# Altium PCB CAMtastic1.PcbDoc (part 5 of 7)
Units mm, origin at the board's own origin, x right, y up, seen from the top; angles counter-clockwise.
Board outline 150.22 x 135.24 mm, 5 copper layers (Top Layer, Layer 1, Mid-Layer 1, Layer 2, Bottom Layer), stack 0.461 mm thick; 0 components, 362 nets, 2885 pads, 0 vias.
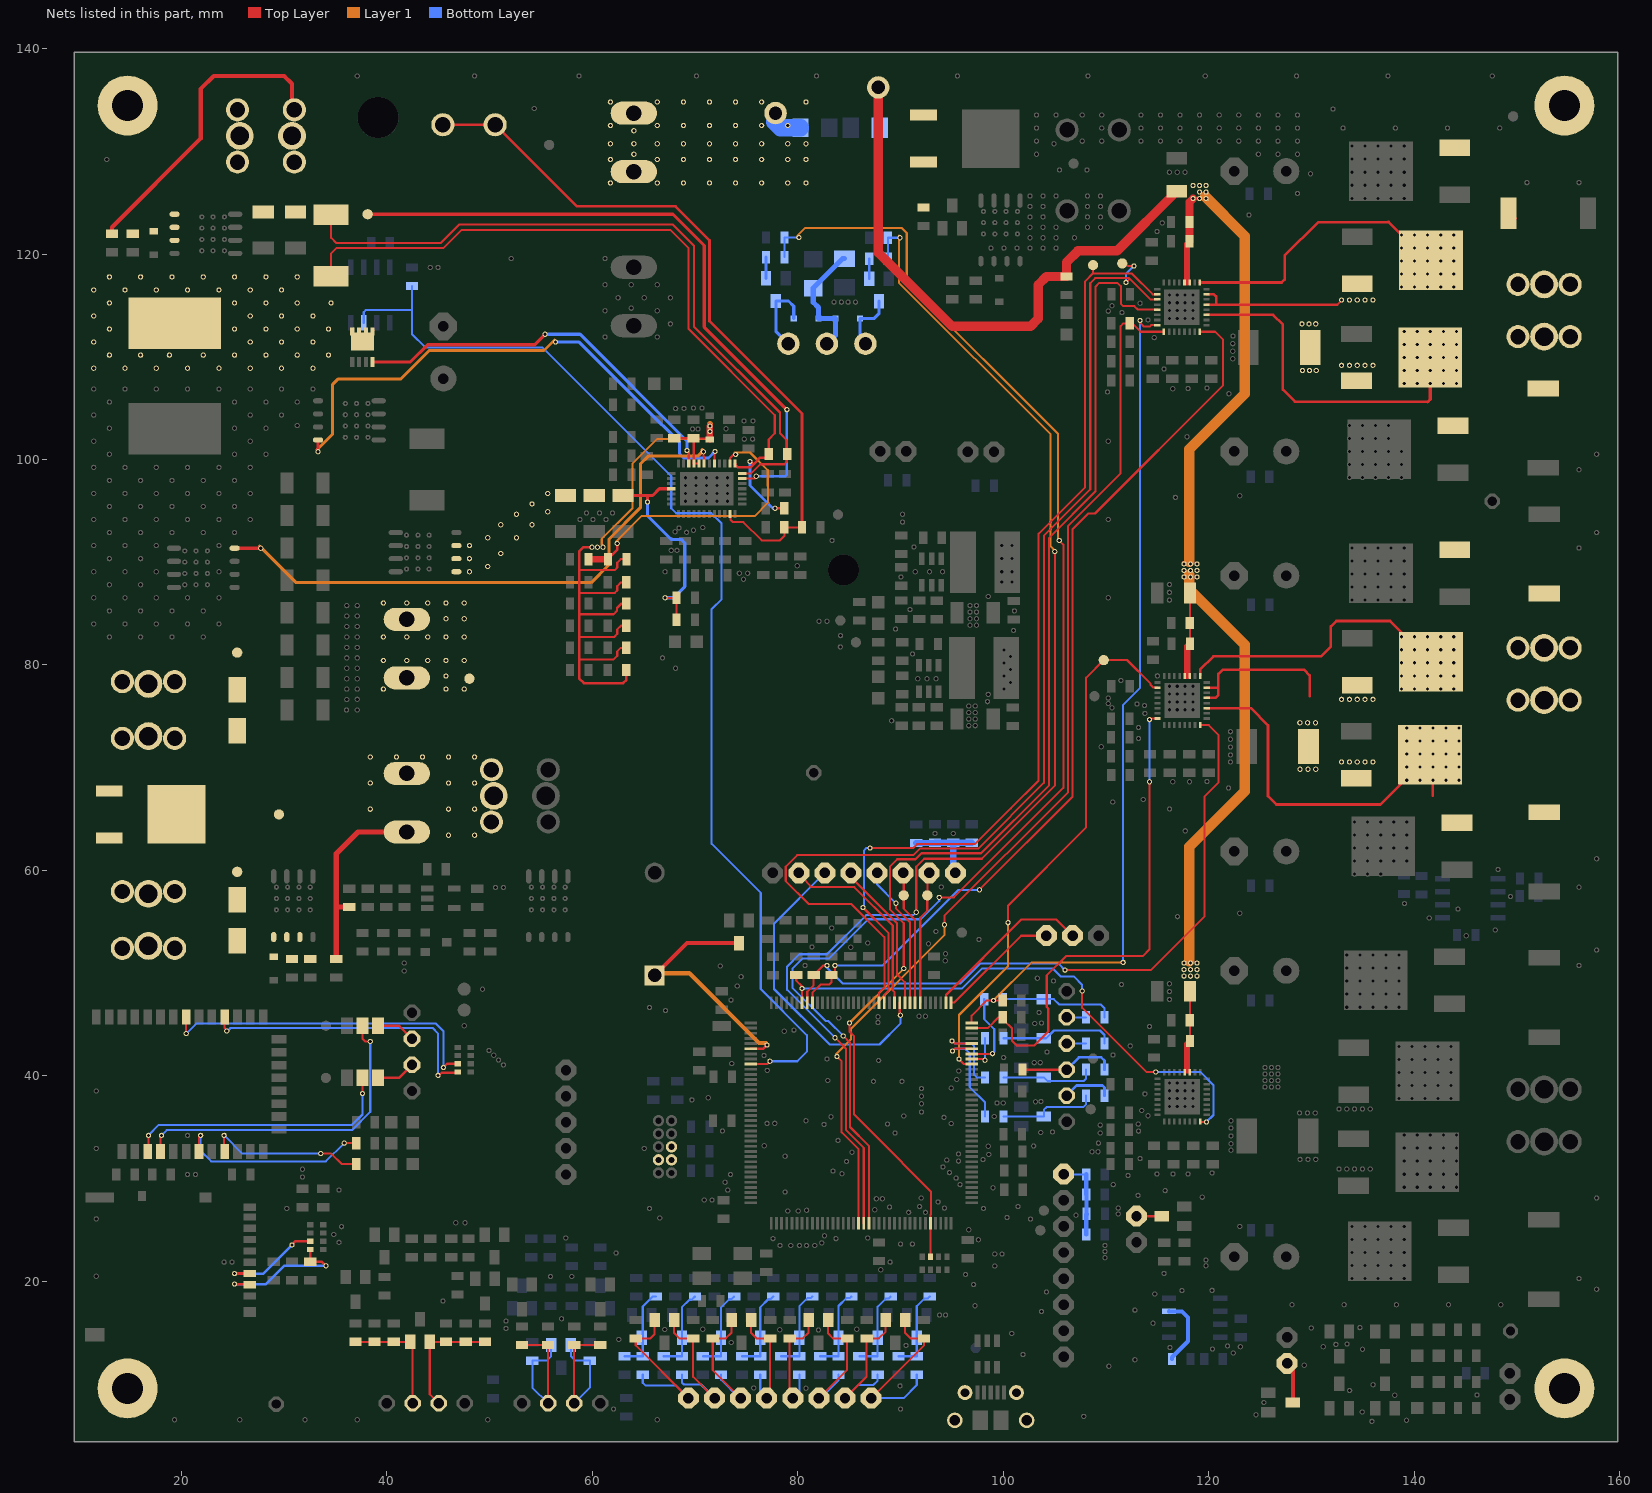
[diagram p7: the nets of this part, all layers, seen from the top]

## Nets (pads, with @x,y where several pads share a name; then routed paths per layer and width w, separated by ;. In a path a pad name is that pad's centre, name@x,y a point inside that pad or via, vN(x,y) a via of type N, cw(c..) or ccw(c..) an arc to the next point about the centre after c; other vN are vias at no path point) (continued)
$Net72: pad.1@25.167,19.736 pad.1@26.642,19.668 pad.1@32.533,21.906 pad.1@32.533,23.108 pad.1@34.057,21.514 | length 14
  Top Layer w0.254: pad.1@25.167,19.736 25.201,19.702 26.608,19.702 pad.1@26.642,19.668 ; pad.1@32.533,23.108 pad.1@32.533,21.906 33.665,21.906 pad.1@34.057,21.514
  Bottom Layer w0.254: pad.1@25.167,19.736 28.215,19.736 29.993,21.514 pad.1@34.057,21.514
$Net73: pad.1@24.151,34.214 pad.1@24.204,32.631 pad.1@33.549,32.436 pad.1@37.001,31.42 | length 15.6
  Top Layer w0.203: pad.1@24.151,34.214 24.151,32.685 pad.1@24.204,32.631 ; pad.1@33.549,32.436 34.565,32.436 35.581,31.42 pad.1@37.001,31.42
  Bottom Layer w0.203: pad.1@24.151,34.214 25.929,32.436 pad.1@33.549,32.436
$Net74: pad.1@21.705,32.631 pad.1@21.865,34.214 pad.1@35.835,33.452 pad.1@37.001,33.452 | length 19.5
  Top Layer w0.203: pad.1@21.705,32.631 21.705,34.054 pad.1@21.865,34.214 ; pad.1@35.835,33.452 pad.1@37.001,33.452
  Bottom Layer w0.203: pad.1@21.865,34.214 21.865,32.69 22.881,31.674 34.057,31.674 pad.1@35.835,33.452
$Net75: pad.1@16.706,32.631 pad.1@16.785,34.214 pad.1@37.613,38.278 pad.1@37.613,39.802 | length 26.8
  Top Layer w0.203: pad.1@16.706,32.631 16.785,32.71 pad.1@16.785,34.214 ; pad.1@37.613,38.278 pad.1@37.613,39.802
  Bottom Layer w0.203: pad.1@16.785,34.214 17.801,35.23 36.597,35.23 37.613,36.246 pad.1@37.613,38.278
$Net76: pad.1@24.204,45.738 pad.1@24.405,44.374 pad.1@44.979,40.056 pad.1@46.893,40.38 | length 28.5
  Top Layer w0.203: pad.1@24.204,45.738 24.204,44.657 24.405,44.456 pad.1@24.405,44.374 ; pad.1@44.979,40.056 45.061,40.056 45.315,40.31 46.823,40.31 pad.1@46.893,40.38
  Bottom Layer w0.203: pad.1@24.405,44.374 24.487,44.374 24.773,44.66 44.438,44.66 44.979,44.12 pad.1@44.979,40.056
$Net77: pad.1@25.167,20.752 pad.1@26.642,20.768 pad.1@30.755,23.546 pad.1@32.533,23.908 | length 10.2
  Top Layer w0.254: pad.1@25.167,20.752 25.174,20.76 26.634,20.76 pad.1@26.642,20.768 ; pad.1@30.755,23.546 31.117,23.908 pad.1@32.533,23.908
  Bottom Layer w0.254: pad.1@25.167,20.752 27.961,20.752 pad.1@30.755,23.546
$Net78: pad.1@17.956,32.631 pad.1@18.055,34.214 pad.1@37.613,44.882 pad.1@38.375,43.358 | length 31.9
  Top Layer w0.203: pad.1@17.956,32.631 17.956,34.115 pad.1@18.055,34.214 ; pad.1@37.613,44.882 37.613,43.612 37.867,43.358 pad.1@38.375,43.358
  Bottom Layer w0.203: pad.1@18.055,34.214 18.563,34.722 36.597,34.722 38.375,36.5 pad.1@38.375,43.358
$Net79: pad.1@20.455,44.12 pad.1@20.455,45.738 pad.1@45.487,40.818 pad.1@46.893,41.18 | length 32.5
  Top Layer w0.203: pad.1@20.455,44.12 pad.1@20.455,45.738 ; pad.1@45.487,40.818 45.849,41.18 pad.1@46.893,41.18
  Bottom Layer w0.203: pad.1@20.455,44.12 21.425,45.09 44.77,45.09 45.487,44.374 pad.1@45.487,40.818
$Net80: pad.1@19.524,65.456 pad.1@29.485,65.456 pad.1@35.073,51.37 pad.1@36.343,56.428 pad.1@38.375,65.964 pad.1@38.375,68.504 pad.1@38.375,71.044 pad.1@40.915,71.044 pad.1@41.931,63.742 pad.1@41.931,69.442 pad.1@43.455,71.044 pad.1@45.995,63.424 pad.1@45.995,65.964 pad.1@45.995,68.504 pad.1@45.995,71.044 pad.1@48.535,63.424 pad.1@48.535,65.964 pad.1@48.535,68.504 pad.1@48.535,71.044 pad.1@50.17,64.718 pad.1@50.17,69.798 pad.1@50.395,67.258 | length 19.3
  Top Layer w0.508: pad.1@35.073,51.37 35.073,56.508 ; pad.1@36.343,56.428 35.153,56.428 35.073,56.508 ; pad.1@41.931,63.742 37.169,63.742 35.073,61.646 35.073,56.508
$Net82: pad.1@86.339,56.388 pad.1@87.024,62.179 pad.1@88.411,47.142 pad.1@108.729,118.923 pad.1@114.98,116.083 | length 95.3
  Top Layer w0.203: pad.1@86.339,56.388 88.828,53.899 88.828,48.311 88.411,47.894 pad.1@88.411,47.142 ; pad.1@87.024,62.179 91.241,62.179 91.622,62.56 97.21,62.56 100.715,66.04 103.433,68.758 103.433,92.786 107.954,97.307 107.954,117.348 108.716,118.11 ; pad.1@108.729,118.923 108.729,118.123 108.716,118.11 ; pad.1@114.98,116.083 114.888,116.078 114.533,116.078 112.501,118.11 108.716,118.11
  Bottom Layer w0.203: pad.1@86.339,56.388 86.44,56.49 86.44,61.951 86.669,62.179 pad.1@87.024,62.179
$Net83: pad.1@87.705,59.758 pad.1@89.539,56.807 pad.1@90.911,47.142 | length 13.9
  Top Layer w0.203: pad.1@89.539,56.807 89.539,56.337 90.911,54.966 90.911,47.244 pad.1@90.911,47.142
  Bottom Layer w0.203: pad.1@87.705,59.758 87.705,58.641 pad.1@89.539,56.807
$Net84: pad.1@83.621,43.713 pad.1@86.411,25.654 pad.1@88.754,119.558 pad.1@88.754,121.59 pad.1@89.937,121.59 pad.1@91.52,55.931 pad.1@105.008,91.034 | length 126.8
  Top Layer w0.203: pad.1@83.621,43.713 84.662,42.672 84.662,34.747 86.411,32.999 pad.1@86.411,25.654 ; pad.1@91.52,55.931 91.52,60.376 92.282,61.138 97.896,61.138 105.008,68.25 pad.1@105.008,91.034
  Layer 1 w0.203: pad.1@89.83,121.793 89.83,117.221 104.596,102.455 104.596,91.542 pad.1@104.901,91.237
  Bottom Layer w0.203: pad.1@83.621,43.713 78.947,48.387 78.947,50.648 80.141,51.841 82.833,51.841 86.643,55.651 91.241,55.651 pad.1@91.52,55.931 ; pad.1@88.754,119.558 pad.1@88.754,121.59 pad.1@89.937,121.59
$Net85: pad.1@78.705,119.705 pad.1@78.705,121.61 pad.1@80.09,121.615 pad.1@84.408,43.891 pad.1@86.911,25.654 pad.1@93.755,57.379 pad.1@105.439,92.126 | length 136.4
  Top Layer w0.203: pad.1@84.408,43.891 85.069,43.231 85.069,35.027 86.911,33.184 pad.1@86.911,25.654 ; pad.1@93.755,57.379 95.178,57.379 105.846,68.047 105.846,91.719 pad.1@105.439,92.126
  Layer 1 w0.203: pad.1@79.984,121.818 80.72,122.555 90.084,122.555 90.592,122.047 90.592,117.221 105.333,102.48 pad.1@105.333,92.329
  Bottom Layer w0.203: pad.1@78.705,119.705 78.705,121.56 pad.1@78.755,121.61 ; pad.1@78.705,121.61 pad.1@78.755,121.61 ; pad.1@80.09,121.615 80.085,121.61 pad.1@78.755,121.61 ; pad.1@84.408,43.891 82.96,45.339 82.706,45.339 79.455,48.59 79.455,50.419 80.471,51.435 83.037,51.435 86.847,55.245 91.952,55.245 93.755,57.048 pad.1@93.755,57.379
$Net86: pad.1@83.799,41.885 pad.1@85.911,25.654 pad.1@94.263,54.712 pad.1@112.311,113.259 pad.1@115.63,112.433 | length 104.2
  Top Layer w0.203: pad.1@83.799,41.885 84.256,41.427 84.256,34.497 85.911,32.842 pad.1@85.911,25.654 ; pad.1@94.263,54.712 94.263,55.575 106.303,67.615 106.303,93.548 111.408,98.654 111.408,112.979 111.688,113.259 pad.1@112.311,113.259 112.551,113.259 113.377,112.433 pad.1@115.63,112.433
  Layer 1 w0.203: pad.1@83.692,42.088 85.165,43.561 85.165,44.602 94.263,53.7 pad.1@94.263,54.712 ; pad.1@94.347,54.712 94.347,54.725 94.36,54.712 pad.1@94.347,54.712
$Net87: pad.1@85.018,45.161 pad.1@90.301,50.444 pad.1@92.898,22.393 pad.1@92.911,25.654 pad.1@114.98,114.583 | length 121.4
  Top Layer w0.203: pad.1@85.018,45.161 85.018,44.323 85.475,43.866 85.475,36.246 87.405,34.315 92.943,28.753 92.943,26.518 92.911,26.486 pad.1@92.911,25.654 92.911,22.405 pad.1@92.898,22.393 ; pad.1@90.301,50.444 90.301,54.864 88.98,56.185 88.98,60.401 89.666,61.087 91.444,61.087 92.028,61.671 97.819,61.671 104.449,68.301 104.449,92.38 108.97,96.901 108.97,116.815 109.351,117.196 111.104,117.196 111.434,116.865 111.434,115.164 111.662,114.935 112.755,114.935 113.106,114.583 pad.1@114.98,114.583
  Layer 1 w0.203: pad.1@85.027,45.152 pad.1@90.311,50.435
$Net88: pad.1@82.625,59.758 pad.1@89.911,47.142 pad.1@89.971,45.898 | length 30.8
  Top Layer w0.203: pad.1@89.911,47.142 89.911,45.958 pad.1@89.971,45.898
  Bottom Layer w0.203: pad.1@82.625,59.758 77.677,54.81 77.677,54.712 77.677,54.635 77.677,48.463 83.087,43.053 87.939,43.053 89.971,45.085 pad.1@89.971,45.898
$Net89: pad.1@95.686,41.631 pad.1@96.905,41.148 pad.1@100.461,54.915 pad.1@109.77,80.48 pad.1@115.005,77.792 | length 52.5
  Top Layer w0.203: pad.1@95.686,41.631 96.168,41.148 pad.1@96.905,41.148 ; pad.1@100.461,54.915 100.461,56.591 108.056,64.186 108.056,78.765 pad.1@109.77,80.48 112.031,80.48 114.304,78.207 114.304,78.105 114.617,77.792 pad.1@115.005,77.792
  Layer 1 w0.203: pad.1@95.686,41.727 95.686,45.924 100.461,50.699 pad.1@100.461,54.915
  Layer 1 w0.254: pad.1@95.686,41.631 pad.1@95.686,41.727
$Net90: pad.1@95.051,42.418 pad.1@96.905,42.648 pad.1@98.215,36.043 | length 10.7
  Top Layer w0.203: pad.1@95.051,42.418 95.281,42.648 pad.1@96.905,42.648
  Bottom Layer w0.203: pad.1@95.051,42.418 95.279,42.647 96.27,42.647 96.727,42.189 96.727,38.913 98.215,37.425 pad.1@98.215,36.043
$Net91: pad.1@95,43.409 pad.1@96.905,43.148 pad.1@98.215,39.853 | length 8.3
  Top Layer w0.203: pad.1@95,43.409 95.26,43.148 pad.1@96.905,43.148
  Bottom Layer w0.203: pad.1@95,43.409 95.26,43.148 96.905,43.148 97.159,42.894 97.159,40.107 97.413,39.853 pad.1@98.215,39.853
$Net92: pad.1@96.905,41.648 pad.1@98.2,41.529 pad.1@98.215,43.663 | length 3.5
  Top Layer w0.203: pad.1@96.905,41.648 98.081,41.648 pad.1@98.2,41.529
  Bottom Layer w0.203: pad.1@98.2,41.529 98.215,41.543 pad.1@98.215,43.663
$Net93: pad.1@96.905,42.148 pad.1@98.139,47.473 pad.1@98.937,42.164 | length 7.8
  Top Layer w0.203: pad.1@96.905,42.148 98.921,42.148 pad.1@98.937,42.164
  Bottom Layer w0.203: pad.1@98.139,47.473 98.139,45.528 99.115,44.552 99.115,42.342 pad.1@98.937,42.164
$Net94: pad.1@96.905,45.148 pad.1@99.039,47.346 pad.1@99.942,47.346 pad.1@111.662,51.054 pad.1@113.313,113.538 pad.1@114.98,113.083 | length 83.8
  Top Layer w0.203: pad.1@96.905,45.148 96.905,45.872 98.378,47.346 pad.1@99.039,47.346 pad.1@99.942,47.346 ; pad.1@113.313,113.538 113.313,113.309 113.694,112.928 114.228,112.928 114.38,113.081 114.837,113.081 pad.1@114.98,113.083
  Layer 1 w0.203: pad.1@99.039,47.346 102.747,51.054 pad.1@111.662,51.054
  Bottom Layer w0.203: pad.1@111.662,51.054 111.662,76.124 113.288,77.749 113.288,113.513 pad.1@113.313,113.538
$Net95: pad.1@81.411,47.142 pad.1@83.265,49.824 pad.1@83.595,50.749 pad.1@97.667,58.115 pad.1@119.13,112.433 | length 88.4
  Top Layer w0.203: pad.1@81.411,47.142 81.411,48.082 82.224,48.895 83.037,48.895 83.265,49.124 pad.1@83.265,49.824 83.595,50.154 pad.1@83.595,50.749 ; pad.1@97.667,58.115 106.735,67.183 106.735,93.218 108.259,94.742 108.919,94.742 121.391,107.213 121.391,111.658 120.616,112.433 pad.1@119.13,112.433
  Bottom Layer w0.203: pad.1@83.595,50.749 88.269,50.749 95.635,58.115 pad.1@97.667,58.115
$Net96: pad.1@80.911,47.142 pad.1@81.538,49.824 pad.1@82.833,50.749 pad.1@105.998,50.292 pad.1@119.155,74.142 | length 65.9
  Top Layer w0.203: pad.1@80.911,47.142 80.911,48.192 81.538,48.819 pad.1@81.538,49.824 82.463,50.749 pad.1@82.833,50.749 ; pad.1@105.998,50.292 114.355,50.292 119.562,55.499 119.562,67.183 120.959,68.58 120.959,73.177 119.994,74.142 pad.1@119.155,74.142
  Bottom Layer w0.203: pad.1@82.833,50.749 82.833,50.521 84.357,48.997 95.813,48.997 97.769,50.952 105.338,50.952 pad.1@105.998,50.292
$Net97: pad.1@79.836,49.824 pad.1@80.395,48.514 pad.1@80.411,47.142 pad.1@107.675,48.26 pad.1@114.837,40.386 pad.1@119.155,35.553 pad.1@119.765,35.509 | length 54.3
  Top Layer w0.203: pad.1@79.836,49.824 79.836,49.276 80.411,48.701 pad.1@80.411,48.463 ; pad.1@80.395,48.514 pad.1@80.411,48.463 ; pad.1@80.411,47.142 pad.1@80.411,48.463 ; pad.1@107.675,48.26 107.675,46.634 113.923,40.386 pad.1@114.837,40.386 ; pad.1@119.155,35.553 119.257,35.509 pad.1@119.765,35.509
  Bottom Layer w0.203: pad.1@80.395,48.514 95.991,48.514 97.946,50.47 104.779,50.47 105.566,49.682 106.836,49.682 107.675,48.844 pad.1@107.675,48.26 ; pad.1@114.837,40.386 119.155,40.386 120.451,39.091 120.451,36.195 pad.1@119.765,35.509
$Net98: pad.1@66.061,49.788 pad.1@74.274,52.926 pad.1@75.417,42.648 pad.1@76.991,43.002 | length 25
  Top Layer w0.254: pad.1@75.417,42.648 76.637,42.648 pad.1@76.991,43.002
  Top Layer w0.406: pad.1@66.061,49.788 69.198,52.926 pad.1@74.274,52.926
  Layer 1 w0.406: pad.1@65.954,49.991 69.43,49.991 76.216,43.205 pad.1@76.885,43.205
$Net99: pad.1@37.74,113.302 pad.1@42.439,116.902 pad.1@75.417,41.148 pad.1@77.271,41.427 | length 111.7
  Top Layer w0.203: pad.1@75.417,41.148 76.992,41.148 pad.1@77.271,41.427
  Bottom Layer w0.203: pad.1@37.74,113.302 37.74,114.351 37.936,114.547 42.439,114.547 ; pad.1@42.439,116.902 42.439,114.547 ; pad.1@77.271,41.427 79.938,41.427 80.878,42.367 80.878,43.967 76.382,48.463 76.382,57.81 71.607,62.586 71.607,85.446 72.572,86.411 72.572,93.777 71.581,94.767 68.152,94.767 67.67,95.25 67.67,98.374 55.122,110.922 43.709,110.922 42.439,112.192 42.439,114.547
$Net100: pad.1@87.825,136.222 pad.1@87.957,132.296 pad.1@92.223,124.522 pad.1@92.223,128.956 pad.1@92.223,133.528 pad.1@106.151,117.816 pad.1@116.872,126.111 pad.1@117.63,117.233 pad.1@117.581,49.708 pad.1@117.581,50.343 pad.1@117.581,50.978 pad.1@117.581,88.57 pad.1@117.581,89.84 pad.1@117.581,89.205 pad.1@117.655,40.353 pad.1@117.655,78.942 pad.1@118.13,117.233 pad.1@118.47,125.4 pad.1@118.47,126.67 pad.1@118.128,121.234 pad.1@118.128,123.114 pad.1@118.153,45.421 pad.1@118.153,84.086 pad.1@118.155,40.353 pad.1@118.155,78.942 pad.1@118.167,48.24 pad.1@118.167,87.007 pad.1@118.178,43.389 pad.1@118.178,82.08 pad.1@118.216,49.708 pad.1@118.216,50.343 pad.1@118.216,50.978 pad.1@118.216,88.57 pad.1@118.216,89.84 pad.1@118.216,89.205 pad.1@118.851,49.708 pad.1@118.851,50.343 pad.1@118.851,50.978 pad.1@118.851,88.57 pad.1@118.851,89.84 pad.1@118.851,89.205 pad.1@119.74,125.4 pad.1@119.74,126.035 pad.1@119.74,126.67 pad.1@119.105,125.4 pad.1@119.105,126.035 pad.1@119.105,126.67 | length 164.8
  Top Layer w0.203: pad.1@116.796,126.035 pad.1@116.872,126.111 ; pad.1@117.63,117.233 117.873,117.233 ; pad.1@117.655,78.942 117.91,78.942 pad.1@118.155,78.942 ; 117.885,40.64 117.655,40.41 pad.1@117.655,40.353 pad.1@118.155,40.353 ; 117.885,117.246 117.873,117.233 ; pad.1@118.128,121.234 pad.1@118.13,121.232 ; pad.1@118.13,117.233 117.873,117.233 ; pad.1@118.155,43.366 pad.1@118.178,43.389 118.179,45.395 pad.1@118.153,45.421 118.153,48.226 pad.1@118.167,48.24 pad.1@118.198,48.209 ; pad.1@118.155,82.056 pad.1@118.178,82.08 118.179,84.061 pad.1@118.153,84.086 118.153,86.993 pad.1@118.167,87.007
  Top Layer w0.61: 117.885,40.64 117.885,43.096 pad.1@118.155,43.366 ; 117.885,117.246 117.885,120.987 pad.1@118.13,121.232 ; 117.911,78.943 117.911,81.812 pad.1@118.155,82.056
  Top Layer w0.762: pad.1@118.128,121.234 118.128,125.058 pad.1@118.47,125.4
  Top Layer w0.914: pad.1@87.825,136.222 87.825,120.146 95.017,112.954 102.637,112.954 103.399,113.716 103.399,117.018 104.197,117.816 pad.1@106.151,117.816 106.151,119.202 107.254,120.305 111.066,120.305 pad.1@116.872,126.111
  Layer 1 w0.203: pad.1@117.474,90.043 pad.1@118.109,90.043
  Layer 1 w1.016: pad.1@118.109,51.181 118.109,62.306 123.494,67.691 123.494,81.991 118.109,87.376 pad.1@118.109,88.773 ; pad.1@118.109,90.043 118.109,101.016 123.494,106.401 123.494,121.742 pad.1@119.633,125.603
$Net101: pad.1@119.805,76.792 pad.1@119.805,77.792 pad.1@128.858,74.371 pad.1@128.884,69.85 pad.1@129.62,74.371 pad.1@129.646,69.85 pad.1@129.702,72.072 pad.1@130.382,74.371 pad.1@130.408,69.85 pad.1@132.922,70.561 pad.1@132.922,76.657 pad.1@133.684,70.561 pad.1@133.684,76.657 pad.1@134.347,68.974 pad.1@134.444,78.017 pad.1@134.446,70.561 pad.1@134.446,76.657 pad.1@135.97,70.561 pad.1@135.97,76.657 pad.1@135.208,70.561 pad.1@135.208,76.657 | length 15.8
  Top Layer w0.254: pad.1@119.805,76.792 120.665,76.792 120.936,77.064 120.936,77.724 ; pad.1@119.805,77.792 120.868,77.792 120.936,77.724 ; 129.823,76.98 129.823,78.994 129.29,79.527 121.342,79.527 120.936,79.121 120.936,77.724
$Net102: pad.1@119.805,75.792 pad.1@139.272,68.783 pad.1@139.272,70.053 pad.1@139.272,71.323 pad.1@139.272,72.593 pad.1@139.272,73.863 pad.1@140.542,68.783 pad.1@140.542,70.053 pad.1@140.542,71.323 pad.1@140.542,72.593 pad.1@140.542,73.863 pad.1@141.527,71.259 pad.1@141.812,68.783 pad.1@141.812,70.053 pad.1@141.812,71.323 pad.1@141.812,72.593 pad.1@141.812,73.863 pad.1@143.082,68.783 pad.1@143.082,70.053 pad.1@143.082,71.323 pad.1@143.082,72.593 pad.1@143.082,73.863 pad.1@144.152,64.63 pad.1@144.352,68.783 pad.1@144.352,70.053 pad.1@144.352,71.323 pad.1@144.352,72.593 pad.1@144.352,73.863 pad.1@150.093,76.581 pad.1@152.633,76.581 pad.1@152.661,65.676 pad.1@155.173,76.581 | length 35.7
  Top Layer w0.254: pad.1@119.805,75.792 124.084,75.792 125.759,74.117 125.759,67.234 126.572,66.421 136.689,66.421 pad.1@141.527,71.259 ; 141.812,67.259 pad.1@141.812,71.323
$Net103: pad.1@119.155,78.942 pad.1@138.764,77.673 pad.1@138.764,78.943 pad.1@138.764,80.213 pad.1@138.764,81.483 pad.1@138.764,82.753 pad.1@140.034,77.673 pad.1@140.034,78.943 pad.1@140.034,80.213 pad.1@140.034,81.483 pad.1@140.034,82.753 pad.1@141.304,77.673 pad.1@141.304,78.943 pad.1@141.304,80.213 pad.1@141.304,81.483 pad.1@141.304,82.753 pad.1@141.624,80.302 pad.1@142.574,77.673 pad.1@142.574,78.943 pad.1@142.574,80.213 pad.1@142.574,81.483 pad.1@142.574,82.753 pad.1@143.844,77.673 pad.1@143.844,78.943 pad.1@143.844,80.213 pad.1@143.844,81.483 pad.1@143.844,82.753 pad.1@143.943,91.198 pad.1@150.093,81.661 pad.1@152.633,81.661 pad.1@152.635,86.952 pad.1@155.173,81.661 | length 27.8
  Top Layer w0.254: pad.1@119.155,78.942 119.155,79.55 120.453,80.848 130.916,80.848 131.881,81.813 131.881,83.744 132.414,84.277 137.648,84.277 pad.1@141.624,80.302 pad.1@141.609,80.316
$Net104: pad.1@96.905,44.648 pad.1@99.942,45.695 pad.1@114.228,68.631 pad.1@114.228,74.676 pad.1@115.005,74.792 | length 50.1
  Top Layer w0.203: pad.1@96.905,44.648 98.475,44.648 99.521,45.695 pad.1@99.942,45.695 100.055,45.415 100.842,44.628 100.842,43.409 101.274,42.977 103.026,42.977 104.373,44.323 104.373,46.558 104.22,46.711 104.22,49.784 106.1,51.664 113.567,51.664 114.228,52.324 pad.1@114.228,68.631 ; pad.1@114.228,74.676 114.344,74.792 pad.1@115.005,74.792
  Bottom Layer w0.203: pad.1@114.228,68.631 pad.1@114.228,74.676
$Net105: pad.1@119.78,114.083 pad.1@139.018,107.391 pad.1@139.018,108.661 pad.1@139.018,109.931 pad.1@139.018,111.201 pad.1@139.018,112.471 pad.1@140.288,107.391 pad.1@140.288,108.661 pad.1@140.288,109.931 pad.1@140.288,111.201 pad.1@140.288,112.471 pad.1@141.553,109.931 pad.1@141.558,107.391 pad.1@141.558,108.661 pad.1@141.558,109.931 pad.1@141.558,111.201 pad.1@141.558,112.471 pad.1@142.828,107.391 pad.1@142.828,108.661 pad.1@142.828,109.931 pad.1@142.828,111.201 pad.1@142.828,112.471 pad.1@143.771,103.275 pad.1@144.098,107.391 pad.1@144.098,108.661 pad.1@144.098,109.931 pad.1@144.098,111.201 pad.1@144.098,112.471 pad.1@150.093,111.963 pad.1@152.559,106.913 pad.1@152.633,111.963 pad.1@155.173,111.963 | length 33.2
  Top Layer w0.254: pad.1@119.78,114.083 126.256,114.083 127.207,113.132 127.207,106.807 128.376,105.639 141.33,105.639 141.38,105.689
  Top Layer w0.305: 141.304,105.613 141.38,105.689 141.558,105.867 pad.1@141.558,109.931
$Net106: pad.1@119.13,117.233 pad.1@138.764,116.789 pad.1@138.764,118.059 pad.1@138.764,119.329 pad.1@138.764,120.599 pad.1@138.764,121.869 pad.1@140.034,116.789 pad.1@140.034,118.059 pad.1@140.034,119.329 pad.1@140.034,120.599 pad.1@140.034,121.869 pad.1@141.304,116.789 pad.1@141.304,118.059 pad.1@141.304,119.329 pad.1@141.304,120.599 pad.1@141.304,121.869 pad.1@141.624,119.405 pad.1@142.574,116.789 pad.1@142.574,118.059 pad.1@142.574,119.329 pad.1@142.574,120.599 pad.1@142.574,121.869 pad.1@143.844,116.789 pad.1@143.844,118.059 pad.1@143.844,119.329 pad.1@143.844,120.599 pad.1@143.844,121.869 pad.1@143.943,130.352 pad.1@149.176,123.977 pad.1@150.093,117.043 pad.1@152.633,117.043 pad.1@155.173,117.043 | length 28.5
  Top Layer w0.203: 137.469,123.114 137.494,123.139 ; pad.1@141.624,119.405 pad.1@141.634,119.416 ; pad.1@149.176,123.977 pad.1@149.915,123.466
  Top Layer w0.254: pad.1@119.13,117.233 127.093,117.233 127.385,117.526 127.385,119.837 130.662,123.114 137.469,123.114 ; 137.494,123.139 pad.1@141.304,119.329
$Net107: pad.1@119.78,115.083 pad.1@119.78,116.083 pad.1@129.061,113.208 pad.1@129.112,108.661 pad.1@129.747,113.208 pad.1@129.798,108.661 pad.1@129.854,110.896 pad.1@130.408,113.208 pad.1@130.458,108.661 pad.1@132.922,109.169 pad.1@132.922,115.519 pad.1@133.684,109.169 pad.1@133.684,115.519 pad.1@134.373,107.646 pad.1@134.444,117.12 pad.1@134.446,109.169 pad.1@134.446,115.519 pad.1@135.97,109.169 pad.1@135.97,115.519 pad.1@135.208,109.169 pad.1@135.208,115.519 | length 15.1
  Top Layer w0.203: 120.703,115.083 120.705,115.085 ; pad.1@129.849,110.902 pad.1@129.854,110.896 ; 132.486,115.083 pad.1@132.922,115.519
  Top Layer w0.254: pad.1@119.78,115.083 120.703,115.083 132.486,115.083 ; pad.1@119.78,116.083 120.496,116.083 120.705,115.875 120.705,115.085
$Net108: pad.1@87.911,47.142 pad.1@111.574,119.088 pad.1@111.942,117.246 pad.1@112.704,118.834 pad.1@114.98,115.583 | length 110.1
  Top Layer w0.203: pad.1@87.911,47.142 87.913,47.145 87.913,48.133 88.421,48.641 88.421,53.492 85.17,56.744 81.03,56.744 78.82,58.953 78.82,60.376 79.938,61.493 91.241,61.493 91.876,62.128 97.54,62.128 103.941,68.529 103.941,92.583 108.462,97.104 108.462,117.17 108.945,117.653 112.247,117.653 ; pad.1@111.574,119.088 112.132,118.834 pad.1@112.704,118.834 ; pad.1@111.942,117.246 112.247,117.551 112.247,117.653 ; pad.1@114.98,115.583 114.939,115.57 114.329,115.57 112.247,117.653
  Bottom Layer w0.203: pad.1@111.942,117.246 111.942,118.072 pad.1@112.704,118.834
$Net109: pad.1@13.229,121.982 pad.1@27.961,124.107 pad.1@30.98,128.956 pad.1@30.98,134.036 pad.1@30.755,131.496 pad.1@31.101,124.107 pad.1@34.565,123.828 pad.1@38.121,123.876 pad.1@74.579,98.155 pad.1@74.579,98.655 pad.1@75.95,98.374 pad.1@78.922,104.851 pad.1@78.958,100.536 | length 163.2
  Top Layer w0.203: pad.1@34.565,123.828 34.565,121.59 35.073,121.082 45.233,121.082 47.011,122.86 67.839,122.86 69.871,120.828 69.871,112.954 78.253,104.572 78.253,102.54 78.958,101.834 pad.1@78.958,100.536 78.922,100.5 78.922,99.797 78.668,99.543 76.331,99.543 75.444,98.655 pad.1@74.579,98.655 ; pad.1@74.604,98.146 75.772,98.146 pad.1@75.975,98.349
  Top Layer w0.254: pad.1@74.578,98.171 74.604,98.146 74.589,98.146 pad.1@74.579,98.155 ; pad.1@75.95,98.374 pad.1@75.975,98.349
  Top Layer w0.305: pad.1@38.121,123.876 67.839,123.876 70.887,120.828 70.887,112.886 pad.1@78.922,104.851
  Top Layer w0.406: pad.1@13.229,121.982 13.229,122.606 21.865,131.242 21.865,136.068 23.135,137.338 29.993,137.338 30.755,136.576 30.755,134.261 pad.1@30.98,134.036
  Bottom Layer w0.254: pad.1@75.95,98.374 78.769,98.374 78.922,98.527 pad.1@78.922,104.851
$Net110: pad.1@11.451,108.89 pad.1@11.451,111.43 pad.1@11.451,113.97 pad.1@11.451,116.51 pad.1@12.975,110.16 pad.1@12.975,112.7 pad.1@12.975,115.24 pad.1@12.975,117.78 pad.1@14.499,108.89 pad.1@14.499,116.51 pad.1@16.023,110.16 pad.1@16.023,117.78 pad.1@17.547,108.89 pad.1@17.547,116.51 pad.1@18.817,110.16 pad.1@19.071,117.78 pad.1@19.325,113.278 pad.1@20.595,108.89 pad.1@20.595,116.51 pad.1@22.119,110.16 pad.1@22.119,117.78 pad.1@23.643,108.89 pad.1@23.643,116.51 pad.1@25.167,110.16 pad.1@25.167,112.7 pad.1@25.167,115.24 pad.1@25.167,117.78 pad.1@26.691,108.89 pad.1@26.691,111.43 pad.1@26.691,113.97 pad.1@26.691,116.51 pad.1@28.215,110.16 pad.1@28.215,112.7 pad.1@28.215,115.24 pad.1@28.215,117.78 pad.1@29.739,108.89 pad.1@29.739,111.43 pad.1@29.739,113.97 pad.1@29.739,116.51 pad.1@31.263,110.16 pad.1@31.263,112.7 pad.1@31.263,115.24 pad.1@31.263,117.78 pad.1@32.787,108.89 pad.1@32.787,111.43 pad.1@32.787,113.97 pad.1@34.311,110.16 pad.1@34.311,112.7 pad.1@34.565,115.24 pad.1@34.565,117.828 pad.1@36.622,112.472 pad.1@37.283,112.472 pad.1@37.613,111.479 pad.1@37.943,112.472 pad.1@38.603,112.472 pad.1@73.877,99.607 pad.1@75.34,99.797 pad.1@77.158,100.536 pad.1@77.779,95.25 pad.1@78.679,95.247 | length 73.5
  Top Layer w0.203: pad.1@34.565,117.828 34.565,120.066 35.073,120.574 45.487,120.574 47.265,122.352 67.585,122.352 69.363,120.574 69.363,112.7 77.745,104.318 77.745,102.54 77.158,101.954 pad.1@77.158,100.536
  Top Layer w0.254: pad.1@73.877,99.607 73.877,99.533 74.172,99.238 75.391,99.238 75.658,99.504 ; pad.1@75.34,99.797 75.366,99.797 75.658,99.504 ; pad.1@77.158,100.536 76.8,100.178 76.331,100.178 75.658,99.504 ; pad.1@77.779,95.25 77.782,95.247 pad.1@78.679,95.247
  Bottom Layer w0.254: pad.1@75.34,99.797 75.34,97.485 77.576,95.25 pad.1@77.779,95.25
$Net111: pad.1@39.645,77.648 pad.1@39.645,80.442 pad.1@39.645,82.728 pad.1@39.645,86.03 pad.1@41.931,78.742 pad.1@41.931,80.442 pad.1@41.931,82.728 pad.1@41.931,84.442 pad.1@41.931,86.03 pad.1@43.963,80.442 pad.1@43.963,82.728 pad.1@43.963,86.03 pad.1@45.741,77.648 pad.1@45.741,78.918 pad.1@45.741,80.442 pad.1@45.741,82.728 pad.1@45.741,84.506 pad.1@45.741,86.03 pad.1@46.757,89.078 pad.1@46.757,90.348 pad.1@46.757,91.618 pad.1@47.519,77.648 pad.1@47.519,80.442 pad.1@47.519,82.728 pad.1@47.519,84.506 pad.1@47.519,86.03 pad.1@48.027,78.664 pad.1@48.027,89.078 pad.1@48.027,90.348 pad.1@48.027,91.618 pad.1@49.805,89.586 pad.1@49.805,92.38 pad.1@51.075,90.856 pad.1@51.075,93.65 pad.1@52.599,92.38 pad.1@52.599,94.666 pad.1@54.123,93.65 pad.1@54.123,95.682 pad.1@55.647,94.92 pad.1@55.647,96.698 pad.1@57.383,96.497 pad.1@60.177,96.497 pad.1@62.971,96.497 pad.1@65.358,95.86 pad.1@67.077,86.538 pad.1@67.674,97.155 pad.1@68.192,84.416 pad.1@68.192,86.538 | length 21.6
  Top Layer w0.203: pad.1@67.077,86.538 pad.1@68.192,86.538 pad.1@68.192,84.416
  Top Layer w0.305: pad.1@62.971,96.497 65.29,96.497 ; pad.1@65.358,95.86 65.358,96.429 65.29,96.497 ; pad.1@67.674,97.155 66.518,97.155 65.86,96.497 65.29,96.497
  Bottom Layer w0.305: pad.1@65.358,95.86 65.358,94.513 67.644,92.227 68.635,92.227 68.99,91.872 68.99,87.63 67.898,86.538 pad.1@67.077,86.538
$Net112: pad.1@59.609,90.304 pad.1@61.518,90.304 pad.1@62.412,91.821 pad.1@73.377,99.607 pad.1@73.943,100.482 | length 28.5
  Top Layer w0.203: pad.1@73.377,99.607 73.385,99.615 73.385,100.127 73.74,100.482 pad.1@73.943,100.482
  Top Layer w0.254: pad.1@61.518,90.304 62.412,91.198 pad.1@62.412,91.821
  Top Layer w0.61: pad.1@59.609,90.304 pad.1@61.518,90.304
  Layer 1 w0.203: pad.1@62.305,92.024 64.769,94.488 75.783,94.488 77.078,95.784 77.063,98.958 75.336,100.686 pad.1@73.837,100.686
$Net113: pad.1@33.293,101.905 pad.1@33.295,100.762 pad.1@56.409,111.43 pad.1@71.877,99.607 pad.1@71.937,100.787 | length 53.8
  Top Layer w0.203: pad.1@71.877,99.607 71.886,99.617 71.886,100.609 71.937,100.66 pad.1@71.937,100.787
  Top Layer w0.305: pad.1@33.293,101.905 33.294,101.904 33.294,100.763 pad.1@33.295,100.762
  Layer 1 w0.305: pad.1@33.188,100.965 34.712,102.489 34.712,107.315 35.22,107.823 41.316,107.823 44.11,110.617 55.286,110.617 pad.1@56.302,111.633
  Bottom Layer w0.305: pad.1@56.409,111.43 58.703,111.43 65.18,104.953 68.457,101.727 68.457,100.584 68.889,100.152 71.302,100.152 pad.1@71.937,100.787
$Net114: pad.1@25.167,91.364 pad.1@27.707,91.364 pad.1@70.794,100.762 pad.1@70.877,99.607 | length 57.7
  Top Layer w0.203: pad.1@70.794,100.762 70.794,100.33 70.87,100.254 70.87,99.614 pad.1@70.877,99.607
  Top Layer w0.305: pad.1@25.167,91.364 pad.1@27.707,91.364
  Layer 1 w0.305: pad.1@27.6,91.567 31.156,88.011 59.867,88.011 61.61,89.754 61.61,92.243 64.668,95.301 64.668,99.568 65.43,100.33 70.256,100.33 70.687,100.762 pad.1@70.687,100.965
$Net115: pad.1@38.603,109.487 pad.1@55.393,112.192 pad.1@69.194,100.889 pad.1@69.377,99.607 | length 38.3
  Top Layer w0.254: pad.1@69.194,100.889 69.371,100.711 69.371,99.613 pad.1@69.377,99.607
  Top Layer w0.305: pad.1@38.603,109.487 42.273,109.487 43.963,111.176 54.377,111.176 pad.1@55.393,112.192
  Bottom Layer w0.305: pad.1@55.393,112.192 58.805,112.192 69.194,101.803 pad.1@69.194,100.889
$Net116: pad.1@59.948,91.465 pad.1@60.481,91.465 pad.1@61.04,91.465 pad.1@63.292,79.509 pad.1@63.292,81.668 pad.1@63.292,83.827 pad.1@63.292,85.986 pad.1@63.292,88.044 pad.1@63.318,90.304 pad.1@67.977,102.072 pad.1@69.831,102.072 pad.1@69.877,99.607 pad.1@70.377,99.607 pad.1@71.429,102.718 pad.1@71.429,103.251 pad.1@71.432,101.948 | length 73.3
  Top Layer w0.203: 58.703,80.543 62.056,80.543 62.412,80.899 62.412,81.331 62.749,81.668 pad.1@63.292,81.668 ; 58.703,82.728 62.107,82.728 62.412,83.033 62.412,83.464 62.775,83.827 pad.1@63.292,83.827 ; 58.703,84.963 58.729,84.938 62.056,84.938 62.386,85.268 62.386,85.547 62.825,85.986 pad.1@63.292,85.986 ; 58.703,87.02 62.183,87.02 62.412,87.249 62.412,87.681 62.775,88.044 pad.1@63.292,88.044 ; 58.703,87.147 58.729,87.122 ; 58.703,89.23 62.158,89.23 62.412,89.484 62.412,89.967 62.749,90.304 pad.1@63.318,90.304 ; pad.1@69.877,99.607 pad.1@70.377,99.607 ; pad.1@69.877,102.026 71.354,102.026 pad.1@71.432,101.948
  Top Layer w0.254: pad.1@59.948,91.465 59.11,91.465 58.703,91.059 58.703,89.23 58.703,87.147 58.703,87.02 58.703,84.963 58.703,82.728 58.703,80.543 58.703,78.689 59.161,78.232 62.996,78.232 63.293,78.529 pad.1@63.292,79.509 ; pad.1@67.977,102.072 pad.1@69.831,102.072 69.877,102.026 pad.1@69.877,99.607
  Top Layer w0.61: pad.1@71.429,103.251 71.432,103.121 pad.1@71.432,101.948
  Layer 1 w0.203: pad.1@60.908,91.669 60.908,92.278 63.906,95.275 63.906,99.619 66.268,101.981 71.068,101.981 71.322,102.235 pad.1@71.433,102.515
  Layer 1 w0.61: pad.1@71.433,102.515 pad.1@71.433,103.429
  Bottom Layer w0.203: pad.1@71.429,102.718 pad.1@71.429,103.251
$Net117: pad.1@61.743,126.924 pad.1@61.743,129.21 pad.1@61.743,130.734 pad.1@61.743,132.512 pad.1@61.743,134.798 pad.1@64.029,128.018 pad.1@64.029,129.718 pad.1@64.029,130.734 pad.1@64.029,132.004 pad.1@64.029,133.718 pad.1@66.315,126.924 pad.1@66.315,129.21 pad.1@66.315,130.734 pad.1@66.315,132.512 pad.1@66.315,134.798 pad.1@68.855,126.924 pad.1@68.855,129.21 pad.1@68.855,130.734 pad.1@68.855,132.512 pad.1@68.855,134.798 pad.1@71.395,126.924 pad.1@71.395,129.21 pad.1@71.395,130.734 pad.1@71.395,132.512 pad.1@71.395,134.798 pad.1@73.935,126.924 pad.1@73.935,129.21 pad.1@73.935,130.734 pad.1@73.935,132.512 pad.1@73.935,134.798 pad.1@76.475,126.924 pad.1@76.475,129.21 pad.1@76.475,130.734 pad.1@76.475,132.512 pad.1@76.475,134.798 pad.1@77.825,133.722 pad.1@79.015,126.924 pad.1@79.015,129.21 pad.1@79.015,130.734 pad.1@79.015,132.512 pad.1@80.255,132.296 pad.1@80.793,126.924 pad.1@80.793,129.21 pad.1@80.793,130.734 pad.1@80.793,134.798 | length 2.8
  Bottom Layer w1.676: pad.1@77.734,132.86 78.298,132.296 pad.1@80.255,132.296
$Net118: pad.1@67.695,31.826
$Net119: pad.1@66.425,31.826
$Net120: pad.1@67.695,33.096
$Net121: pad.1@96.27,9.169
$Net122: pad.1@101.27,9.169
$Net123: pad.1@95.27,6.469
$Net124: pad.1@102.27,6.469
$Net125: pad.1@127.616,12.014 pad.1@128.181,8.204 | length 4
  Top Layer w0.406: pad.1@127.616,12.014 128.181,11.449 pad.1@128.181,8.204
$Net126: pad.1@112.958,26.34 pad.1@115.414,26.34 | length 2.5
  Top Layer w0.203: pad.1@112.958,26.34 pad.1@115.414,26.34
$Net127: pad.1@105.871,30.429 pad.1@108.073,24.562 pad.1@108.073,28.448 pad.1@108.073,30.404 pad.1@108.098,26.568 | length 8.2
  Bottom Layer w0.203: pad.1@105.871,30.429 105.897,30.404 pad.1@108.073,30.404
  Bottom Layer w0.406: pad.1@108.073,24.562 108.073,26.518 108.157,26.518 108.157,26.568 pad.1@108.098,26.568 108.098,28.448 pad.1@108.073,28.448 pad.1@108.073,30.404 pad.1@108.073,30.429
$Net128: pad.1@106.151,38.075 pad.1@109.845,38.075 | length 5
  Bottom Layer w0.254: pad.1@106.151,38.075 107.141,39.065 109.63,39.065 109.845,38.851 pad.1@109.845,38.075
$Net129: pad.1@101.869,40.615 pad.1@106.151,40.615 pad.1@109.845,40.615 | length 9.5
  Top Layer w0.254: pad.1@101.869,40.615 pad.1@106.151,40.615
  Bottom Layer w0.254: pad.1@106.151,40.615 107.344,41.808 109.529,41.808 109.845,41.493 pad.1@109.845,40.615
$Net130: pad.1@87.126,8.636 pad.1@90.438,16.238 pad.1@91.571,10.911 pad.1@92.282,14.442 | length 17.2
  Top Layer w0.203: pad.1@87.126,8.636 92.282,13.792 pad.1@92.282,14.442 92.271,14.453 90.961,14.453 90.438,14.976 pad.1@90.438,16.238
  Bottom Layer w0.203: pad.1@87.126,8.636 90.301,8.636 91.571,9.906 pad.1@91.571,10.911
$Net131: pad.1@84.586,8.636 pad.1@86.694,14.442 pad.1@87.761,10.911 pad.1@88.538,16.238 | length 14.4
  Top Layer w0.203: pad.1@84.586,8.636 86.694,10.744 pad.1@86.694,14.442 86.705,14.453 87.888,14.453 88.538,15.103 pad.1@88.538,16.238
  Bottom Layer w0.203: pad.1@84.586,8.636 85.881,9.931 87.355,9.931 87.761,10.338 pad.1@87.761,10.911
$Net132: pad.1@82.046,8.636 pad.1@82.945,16.238 pad.1@83.951,10.911 pad.1@84.789,14.442 | length 13.5
  Top Layer w0.203: pad.1@82.046,8.636 84.789,11.379 pad.1@84.789,14.442 84.775,14.427 83.443,14.427 82.945,14.925 pad.1@82.945,16.238
  Bottom Layer w0.203: pad.1@82.046,8.636 82.224,8.636 83.951,10.363 pad.1@83.951,10.911
$Net133: pad.1@79.201,14.442 pad.1@79.506,8.636 pad.1@80.141,10.911 pad.1@81.045,16.238 | length 11.8
  Top Layer w0.203: pad.1@79.506,8.636 79.201,8.941 pad.1@79.201,14.442 79.212,14.453 80.471,14.453 81.045,15.027 pad.1@81.045,16.238
  Bottom Layer w0.203: pad.1@79.506,8.636 80.141,9.271 pad.1@80.141,10.911
$Net134: pad.1@75.452,16.238 pad.1@76.331,10.911 pad.1@76.966,8.636 pad.1@77.296,14.442 | length 11.8
  Top Layer w0.203: pad.1@75.452,16.238 75.452,14.976 75.975,14.453 77.285,14.453 pad.1@77.296,14.442 77.296,8.966 pad.1@76.966,8.636
  Bottom Layer w0.203: pad.1@76.331,10.911 76.331,9.271 pad.1@76.966,8.636
$Net135: pad.1@71.708,14.442 pad.1@72.521,10.911 pad.1@73.552,16.238 pad.1@74.426,8.636 | length 13.4
  Top Layer w0.203: pad.1@73.552,16.238 73.552,15.027 72.978,14.453 71.719,14.453 pad.1@71.708,14.442 71.708,11.354 pad.1@74.426,8.636
  Bottom Layer w0.203: pad.1@72.521,10.911 72.521,10.414 74.299,8.636 pad.1@74.426,8.636
$Net136: pad.1@67.959,16.238 pad.1@68.711,10.911 pad.1@69.803,14.442 pad.1@71.886,8.636 | length 14.6
  Top Layer w0.203: pad.1@67.959,16.238 67.959,14.976 68.508,14.427 69.789,14.427 pad.1@69.803,14.442 69.803,10.719 pad.1@71.886,8.636
  Bottom Layer w0.203: pad.1@68.711,10.911 68.711,10.16 68.914,9.957 70.565,9.957 pad.1@71.886,8.636
$Net137: pad.1@64.215,14.442 pad.1@64.901,10.911 pad.1@66.059,16.238 pad.1@69.346,8.636 | length 17.2
  Top Layer w0.203: pad.1@66.059,16.238 66.059,14.874 65.627,14.442 pad.1@64.215,14.442 64.215,13.767 pad.1@69.346,8.636
  Bottom Layer w0.203: pad.1@64.901,10.911 64.901,10.135 65.155,9.881 68.101,9.881 pad.1@69.346,8.636
$Net138: pad.1@57.901,13.8 pad.1@58.221,8.136 pad.1@58.221,13.807 pad.1@59.745,12.283 pad.1@60.761,13.807 | length 16.1
  Top Layer w0.203: pad.1@58.221,8.136 pad.1@58.221,13.807 pad.1@60.761,13.807
  Bottom Layer w0.203: pad.1@57.901,13.8 57.916,13.785 57.916,12.7 58.333,12.283 pad.1@59.745,12.283 59.745,9.66 pad.1@58.221,8.136
$Net139: pad.1@53.141,13.807 pad.1@54.157,12.283 pad.1@55.681,8.136 pad.1@55.681,13.807 pad.1@56.001,13.8 | length 16.1
  Top Layer w0.203: pad.1@53.141,13.807 pad.1@55.681,13.807 pad.1@55.681,8.136
  Bottom Layer w0.203: pad.1@55.681,8.136 54.157,9.66 pad.1@54.157,12.283 55.568,12.283 55.986,12.7 55.986,13.785 pad.1@56.001,13.8
$Net140: pad.1@44.159,14.115 pad.1@45.038,8.136 pad.1@45.749,14.111 pad.1@47.654,14.111 pad.1@49.534,14.111 | length 11.7
  Top Layer w0.203: pad.1@45.038,8.136 44.159,9.015 pad.1@44.159,14.115 45.746,14.115 pad.1@45.749,14.111 pad.1@47.654,14.111 pad.1@49.534,14.111
$Net141: pad.1@36.936,14.111 pad.1@38.79,14.111 pad.1@40.669,14.111 pad.1@42.26,14.115 pad.1@42.498,8.136 | length 11.4
  Top Layer w0.203: pad.1@36.936,14.111 pad.1@38.79,14.111 pad.1@40.669,14.111 42.256,14.111 pad.1@42.26,14.115 42.498,13.876 pad.1@42.498,8.136
$Net142: pad.1@39.137,39.802 pad.1@42.439,41.072 | length 3.8
  Top Layer w0.254: pad.1@39.137,39.802 41.169,39.802 pad.1@42.439,41.072
$Net143: pad.1@39.137,44.882 pad.1@42.439,43.612 | length 3.8
  Top Layer w0.254: pad.1@39.137,44.882 41.169,44.882 pad.1@42.439,43.612
$Net144: pad.1@80.085,59.758 pad.1@89.411,47.142 | length 18.9
  Top Layer w0.203: pad.1@80.085,59.758 81.309,58.369 85.5,58.369 89.234,54.635 89.234,48.336 89.411,48.16 pad.1@89.411,47.142
$Net145: pad.1@85.165,59.758 pad.1@90.411,47.142 | length 14.8
  Top Layer w0.203: pad.1@85.165,59.758 85.165,59.34 89.641,54.864 89.641,49.886 90.411,49.115 pad.1@90.411,47.142
$Net146: pad.1@90.245,59.758 pad.1@90.301,57.569 pad.1@91.411,47.142 | length 13.1
  Top Layer w0.203: pad.1@90.245,59.758 90.301,59.701 pad.1@90.301,57.569 90.301,56.286 91.411,55.177 pad.1@91.411,47.142
$Net147: pad.1@91.911,47.142 pad.1@92.6,57.569 pad.1@92.785,59.758 | length 13
  Top Layer w0.203: pad.1@91.911,47.142 91.911,55.407 92.587,56.083 92.587,57.556 pad.1@92.6,57.569 92.6,59.573 pad.1@92.785,59.758
$Net148: pad.1@91.52,62.676 pad.1@93.349,62.702 pad.1@95.127,62.702 pad.1@95.325,59.758 pad.1@96.93,62.702 | length 8.4
  Bottom Layer w0.203: pad.1@93.324,62.676 pad.1@93.349,62.702
  Bottom Layer w0.61: pad.1@91.52,62.676 pad.1@93.324,62.676 ; pad.1@93.349,62.702 pad.1@95.127,62.702 ; pad.1@95.325,59.758 95.127,59.955 pad.1@95.127,62.702 ; pad.1@96.93,62.702 pad.1@95.127,62.702
$Net149: pad.1@94.911,47.142 pad.1@104.195,53.645 | length 12
  Top Layer w0.203: pad.1@94.911,47.142 95.229,47.142 101.731,53.645 pad.1@104.195,53.645
$Net150: pad.1@94.411,47.142 pad.1@106.735,53.645 | length 16.8
  Top Layer w0.203: pad.1@94.411,47.142 94.411,47.874 101.756,55.22 105.16,55.22 pad.1@106.735,53.645
$Net151: pad.1@106.151,45.695 pad.1@108.045,45.695 | length 1.9
  Bottom Layer w0.203: pad.1@106.151,45.695 pad.1@108.045,45.695
$Net152: pad.1@106.151,43.155 pad.1@108.045,43.155 | length 1.9
  Bottom Layer w0.203: pad.1@106.151,43.155 pad.1@108.045,43.155
$Net153: pad.1@77.855,115.43 pad.1@79.075,111.272 pad.1@79.593,113.716 | length 7.8
  Bottom Layer w0.305: pad.1@79.075,111.272 77.855,112.491 pad.1@77.855,115.43 79.079,115.43 79.593,114.916 pad.1@79.593,113.716
$Net154: pad.1@81.487,116.685 pad.1@81.992,113.716 pad.1@82.825,111.272 pad.1@83.657,113.716 pad.1@84.535,119.561 | length 11.9
  Bottom Layer w0.508: pad.1@82.825,111.272 83.657,112.104 pad.1@83.657,113.716 pad.1@81.992,113.716 81.992,114.802 81.487,115.307 pad.1@81.487,116.685 84.364,119.561 pad.1@84.535,119.561
$Net155: pad.1@86.056,113.716 pad.1@86.575,111.272 pad.1@87.905,115.41 | length 5.9
  Bottom Layer w0.305: pad.1@86.575,111.272 86.056,111.79 pad.1@86.056,113.716 87.397,113.716 87.905,114.224 pad.1@87.905,115.41
$Net156: pad.1@14.245,52.421 pad.1@14.245,72.851 pad.1@16.785,52.646 pad.1@16.785,73.076 pad.1@19.325,52.421 pad.1@19.325,72.851 pad.1@25.421,53.152 pad.1@25.421,73.582 pad.1@28.977,51.62 pad.1@28.977,53.518 pad.1@30.247,53.518 pad.1@30.755,51.37 pad.1@31.517,53.518 pad.1@32.533,51.37
$Net157: pad.1@12.975,63.17 pad.1@14.245,57.951 pad.1@16.785,57.726 pad.1@19.325,57.951 pad.1@25.421,57.152 pad.1@25.421,59.868
$Net158: pad.1@12.975,67.742 pad.1@14.245,78.381 pad.1@16.785,78.156 pad.1@19.325,78.381 pad.1@25.421,77.582 pad.1@25.421,81.204
$Net159: pad.1@45.445,132.588 pad.1@50.525,132.588 pad.1@73.377,94.703 pad.1@78.679,93.396 pad.1@80.401,93.396 | length 71.7
  Top Layer w0.203: pad.1@73.377,94.703 73.425,94.654 73.425,94.159 73.681,93.904 74.697,93.904 76.475,92.126 78.253,92.126 78.679,92.552 pad.1@78.679,93.396 pad.1@80.401,93.396
  Top Layer w0.254: pad.1@45.445,132.588 pad.1@50.525,132.588 58.475,124.638 68.093,124.638 71.395,121.336 71.395,113.462 80.401,104.456 pad.1@80.401,93.396
$Net160: pad.1@15.261,121.982 pad.1@17.293,122.232 pad.1@19.323,121.336 pad.1@19.323,122.606 pad.1@19.323,123.876 pad.1@25.45,128.956 pad.1@25.45,134.036 pad.1@25.675,131.496
$Net161: pad.1@154.613,9.576
$Net162: pad.1@14.753,9.576
$Net163: pad.1@14.753,134.451
$Net164: pad.1@154.613,134.451
$Net165: pad.1@100.015,36.043 pad.1@103.949,36.043 pad.1@108.045,38.075 | length 9.8
  Bottom Layer w0.203: pad.1@100.015,36.043 pad.1@103.949,36.043 103.949,36.711 104.195,36.957 107.776,36.957 108.056,37.236 108.056,38.064 pad.1@108.045,38.075
$Net166: pad.1@100.015,39.853 pad.1@103.949,39.853 pad.1@108.045,40.615 | length 9.2
  Bottom Layer w0.203: pad.1@100.015,39.853 pad.1@103.949,39.853 104.304,39.497 107.802,39.497 108.056,39.751 108.056,40.604 pad.1@108.045,40.615
$Net167: pad.1@76.905,117.63 pad.1@76.905,119.705 | length 2.1
  Bottom Layer w0.305: pad.1@76.905,117.63 pad.1@76.905,119.705
$Net168: pad.1@99.939,47.473 pad.1@103.949,47.473 pad.1@109.845,45.695 | length 11.2
  Bottom Layer w0.203: pad.1@99.939,47.473 pad.1@103.949,47.473 104.906,47.473 105.414,46.965 109.453,46.965 109.845,46.573 pad.1@109.845,45.695
$Net169: pad.1@100.015,43.663 pad.1@103.949,43.663 pad.1@109.845,43.155 | length 11.2
  Bottom Layer w0.203: pad.1@100.015,43.663 pad.1@103.949,43.663 104.169,43.663 104.931,44.425 109.402,44.425 109.845,43.982 pad.1@109.845,43.155
$Net170: pad.1@116.124,17.094 pad.1@116.404,12.446 | length 6.8
  Bottom Layer w0.406: pad.1@116.124,17.094 116.15,17.069 117.377,17.069 117.962,16.485 117.962,14.173 116.404,12.615 pad.1@116.404,12.446
$Net171: pad.1@86.955,117.61 pad.1@86.955,119.558 | length 1.9
  Bottom Layer w0.254: pad.1@86.955,117.61 pad.1@86.955,119.558
$Net172: pad.1@63.123,12.711 pad.1@64.791,14.529 pad.1@64.901,12.711 pad.1@66.171,18.531 | length 8.3
  Bottom Layer w0.203: pad.1@63.123,12.711 pad.1@64.901,12.711 64.901,14.521 64.901,17.551 65.881,18.531 pad.1@66.171,18.531
$Net173: pad.1@89.793,12.711 pad.1@91.571,12.711 pad.1@91.571,14.521 pad.1@92.841,18.531 | length 8.3
  Bottom Layer w0.203: pad.1@89.793,12.711 pad.1@91.571,12.711 pad.1@91.571,14.521 91.571,17.577 92.333,18.339 92.649,18.339 pad.1@92.841,18.531
$Net174: pad.1@70.743,12.711 pad.1@72.521,12.711 pad.1@72.521,14.521 pad.1@73.791,18.531 | length 8.3
  Bottom Layer w0.203: pad.1@70.743,12.711 pad.1@72.521,12.711 72.496,14.496 pad.1@72.521,14.521 72.521,17.475 73.308,18.263 73.523,18.263 pad.1@73.791,18.531
$Net175: pad.1@66.933,12.711 pad.1@68.711,12.711 pad.1@68.711,14.521 pad.1@69.981,18.531 | length 8.2
  Bottom Layer w0.203: pad.1@66.933,12.711 pad.1@68.711,12.711 pad.1@68.711,14.521 68.711,17.475 69.448,18.212 69.662,18.212 pad.1@69.981,18.531
$Net176: pad.1@82.173,12.711 pad.1@83.951,12.711 pad.1@83.951,14.521 pad.1@85.221,18.531 | length 8.3
  Bottom Layer w0.203: pad.1@82.173,12.711 pad.1@83.951,12.711 pad.1@83.951,14.521 83.951,17.602 84.738,18.39 85.08,18.39 pad.1@85.221,18.531
$Net177: pad.1@85.983,12.711 pad.1@87.761,12.711 pad.1@87.761,14.521 pad.1@89.031,18.531 | length 8.3
  Bottom Layer w0.203: pad.1@85.983,12.711 pad.1@87.761,12.711 pad.1@87.761,14.521 87.761,17.526 88.548,18.313 88.813,18.313 pad.1@89.031,18.531
$Net178: pad.1@78.363,12.711 pad.1@80.141,12.711 pad.1@80.141,14.521 pad.1@81.411,18.531 | length 8.3
  Bottom Layer w0.203: pad.1@78.363,12.711 pad.1@80.141,12.711 pad.1@80.141,14.521 80.141,17.577 80.928,18.364 81.244,18.364 pad.1@81.411,18.531
$Net179: pad.1@74.553,12.711 pad.1@76.331,12.711 pad.1@76.331,14.521 pad.1@77.601,18.531 | length 8.2
  Bottom Layer w0.203: pad.1@74.553,12.711 pad.1@76.331,12.711 pad.1@76.331,14.521 76.331,17.475 77.144,18.288 77.358,18.288 pad.1@77.601,18.531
